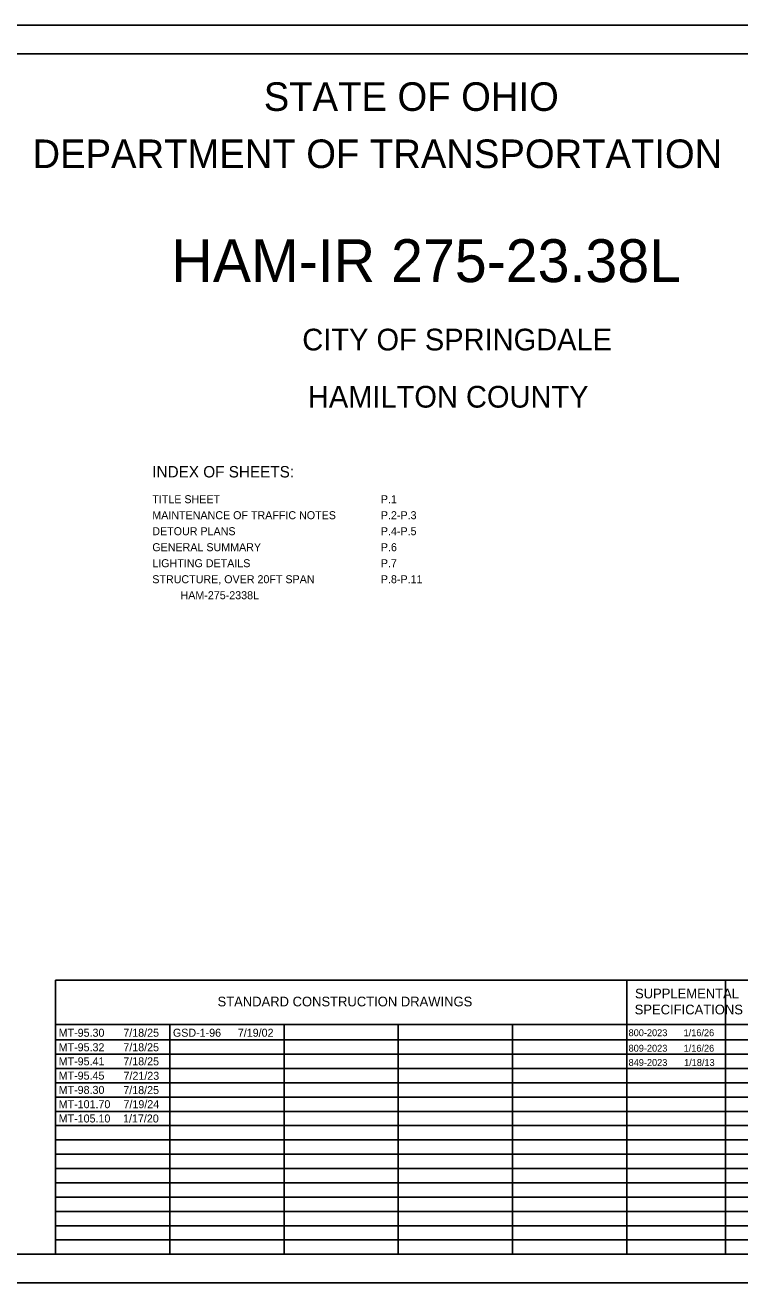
# Model space of a CAD drawing. Extents: x 0 to 34, y -6.8 to 22.
# Drawn here: x 9.62 to 22.13, y 0 to 22 of the extents above; entities that cross this region are included whole.
import ezdxf

# ---------------------------------------------------------------- set-up
doc = ezdxf.new("R2010")
doc.units = 0
for name, color, linetype in [('GM_X_County', 7, 'Continuous'), ('GM_X_Minor_Lake', 7, 'Continuous'), ('GM_X_Minor_Lake_Text', 7, 'Continuous'), ('GM_X_Minor_River_Text', 7, 'Continuous')]:
    doc.layers.add(name, color=color, linetype=linetype)

msp = doc.modelspace()

# ---------------------------------------------------------------- linework, layer by layer
at = {"layer": 'GM_X_County'}
msp.add_lwpolyline([(0, 0), (34, 0), (34, 22), (0, 22)], close=True, dxfattribs=at)
at = {"layer": 'GM_X_Minor_Lake_Text'}
for p, q in [((10.15, 5.292), (23.6, 5.292)), ((10.15, 0.5), (10.15, 5.292)), ((20.15, 0.5), (20.15, 5.292)), ((21.875, 0.5), (21.875, 5.292)), ((10.15, 4.521), (23.6, 4.521)), ((12.15, 0.5), (12.15, 4.521)), ((14.15, 0.5), (14.15, 4.521)), ((16.15, 0.5), (16.15, 4.521)), ((18.15, 0.5), (18.15, 4.521)), ((10.15, 4.25), (23.6, 4.25)), ((10.15, 4), (23.6, 4)), ((10.15, 3.75), (23.6, 3.75)), ((10.15, 3.5), (23.6, 3.5)), ((10.15, 3.25), (23.6, 3.25)), ((10.15, 3), (23.6, 3)), ((10.15, 2.75), (23.6, 2.75)), ((10.15, 2.5), (23.6, 2.5)), ((10.15, 2.25), (23.6, 2.25)), ((10.15, 2), (23.6, 2)), ((10.15, 1.75), (23.6, 1.75)), ((10.15, 1.5), (23.6, 1.5)), ((10.15, 1.25), (23.6, 1.25)), ((10.15, 1), (23.6, 1)), ((10.15, 0.75), (23.6, 0.75))]:
    msp.add_line(p, q, dxfattribs=at)
at = {"layer": 'GM_X_Minor_River_Text'}
msp.add_lwpolyline([(1.5, 21.5), (33.5, 21.5), (33.5, 0.5), (1.5, 0.5)], close=True, dxfattribs=at)

# ---------------------------------------------------------------- texts
at = {"layer": 'GM_X_Minor_Lake'}
for s, height, p in [('STATE OF OHIO', 0.5, (13.795, 20.5)), ('DEPARTMENT OF TRANSPORTATION', 0.5, (9.747, 19.5)), ('HAM-IR 275-23.38L', 0.75, (12.179, 17.505)), ('CITY OF SPRINGDALE', 0.38, (14.469, 16.31)), ('HAMILTON COUNTY', 0.38, (14.567, 15.31)), ('INDEX OF SHEETS:', 0.2, (11.844, 14.088)), ('TITLE SHEET', 0.14, (11.844, 13.638)), ('P.1', 0.14, (15.844, 13.638)), ('MAINTENANCE OF TRAFFIC NOTES', 0.14, (11.844, 13.358)), ('P.2-P.3', 0.14, (15.844, 13.358)), ('DETOUR PLANS', 0.14, (11.844, 13.078)), ('P.4-P.5', 0.14, (15.844, 13.078)), ('GENERAL SUMMARY', 0.14, (11.844, 12.798)), ('P.6', 0.14, (15.844, 12.798)), ('LIGHTING DETAILS', 0.14, (11.844, 12.518)), ('P.7', 0.14, (15.844, 12.518)), ('STRUCTURE, OVER 20FT SPAN', 0.14, (11.844, 12.238)), ('P.8-P.11', 0.14, (15.844, 12.238)), ('HAM-275-2338L', 0.14, (12.338, 11.958)), ('SUPPLEMENTAL', 0.17, (20.293, 4.976)), ('STANDARD CONSTRUCTION DRAWINGS', 0.17, (12.986, 4.836)), ('SPECIFICATIONS', 0.17, (20.287, 4.696)), ('MT-95.30', 0.14, (10.205, 4.305)), ('7/18/25', 0.14, (11.337, 4.305)), ('GSD-1-96', 0.14, (12.205, 4.305)), ('7/19/02', 0.14, (13.341, 4.305)), ('800-2023', 0.12, (20.18, 4.315)), ('1/16/26', 0.12, (21.143, 4.315)), ('MT-95.32', 0.14, (10.205, 4.051)), ('7/18/25', 0.14, (11.337, 4.051)), ('809-2023', 0.12, (20.18, 4.044)), ('1/16/26', 0.12, (21.143, 4.044)), ('MT-95.41', 0.14, (10.205, 3.805)), ('7/18/25', 0.14, (11.337, 3.805)), ('849-2023', 0.12, (20.18, 3.794)), ('1/18/13', 0.12, (21.151, 3.794)), ('MT-95.45', 0.14, (10.205, 3.555)), ('7/21/23', 0.14, (11.34, 3.552)), ('MT-98.30', 0.14, (10.205, 3.305)), ('7/18/25', 0.14, (11.337, 3.302)), ('MT-101.70', 0.14, (10.205, 3.055)), ('7/19/24', 0.14, (11.34, 3.055)), ('MT-105.10', 0.14, (10.205, 2.805)), ('1/17/20', 0.14, (11.332, 2.805))]:
    msp.add_text(s, height=height, dxfattribs=at).set_placement(p)

doc.saveas('drawing.dxf')
